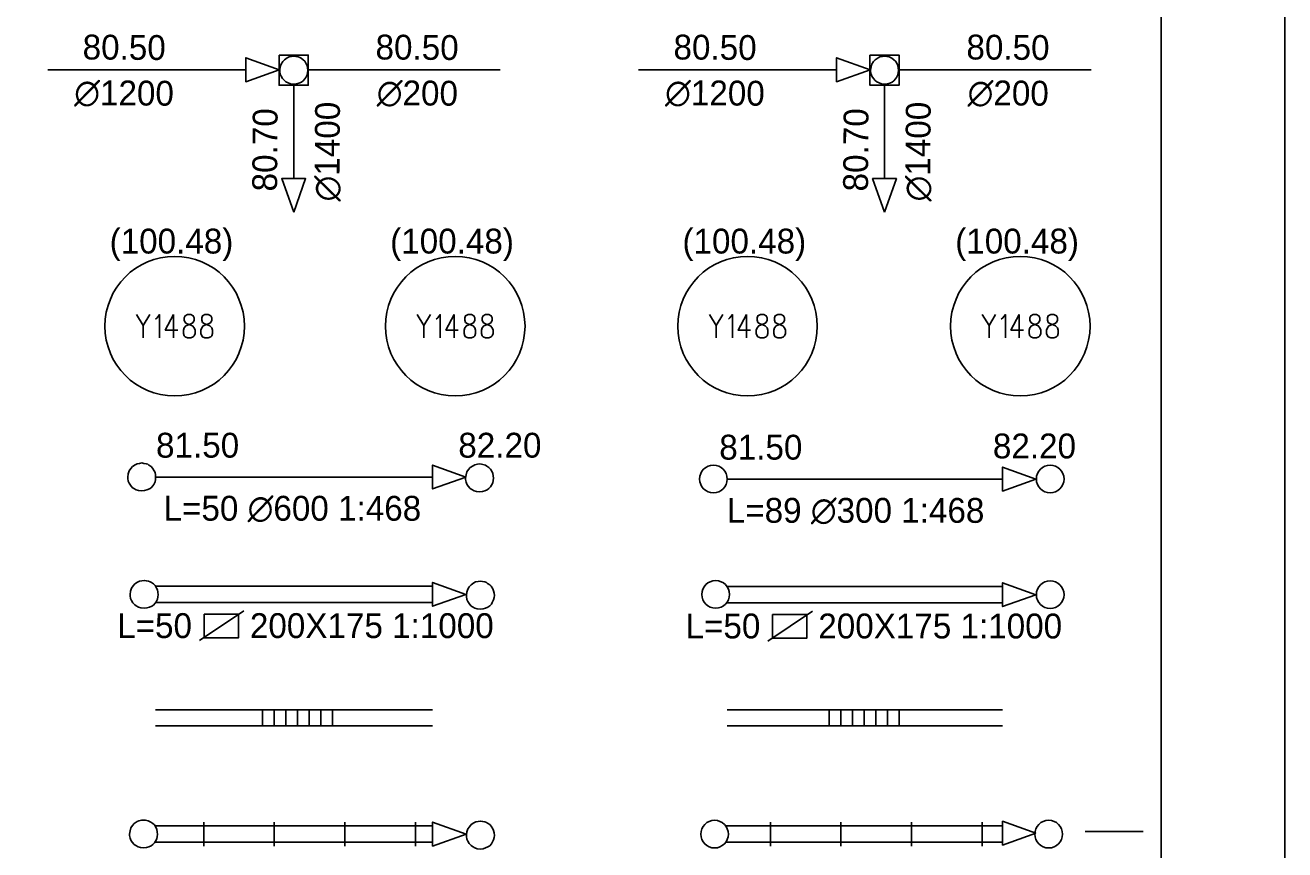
# Model space of a CAD drawing. Extents: x -10 to 1145, y -10 to 821.
# Drawn here: x 1043 to 1145, y 616.2 to 683 of the extents above; entities that cross this region are included whole.
import ezdxf

# ---------------------------------------------------------------- set-up
doc = ezdxf.new("R2010")
doc.units = 0
for name, color, linetype in [('Level 1', 7, 'Continuous'), ('Level 10', 7, 'Continuous'), ('Level 11', 7, 'Continuous'), ('Level 12', 7, 'Continuous'), ('Level 13', 7, 'Continuous'), ('Level 15', 7, 'Continuous'), ('Level 16', 7, 'Continuous'), ('Level 17', 7, 'Continuous'), ('Level 2', 7, 'Continuous'), ('Level 51', 7, 'Continuous'), ('Level 52', 7, 'Continuous'), ('Level 9', 7, 'Continuous')]:
    doc.layers.add(name, color=color, linetype=linetype)

msp = doc.modelspace()

# ---------------------------------------------------------------- linework, layer by layer
at = {"layer": 'Level 1'}
msp.add_line((1133.52, 617.71), (1128.82, 617.71), dxfattribs=at)
at = {"layer": 'Level 10'}
for points in [[(1063.61, 679.35), (1063.61, 679.21), (1063.65, 678.99), (1063.73, 678.83), (1063.84, 678.65), (1063.98, 678.48), (1064.11, 678.39), (1064.3, 678.29), (1064.49, 678.22), (1064.74, 678.2), (1064.97, 678.22), (1065.16, 678.28), (1065.36, 678.36), (1065.5, 678.46), (1065.64, 678.61), (1065.71, 678.73), (1065.82, 678.93), (1065.86, 679.13), (1065.88, 679.3), (1065.86, 679.5), (1065.82, 679.69), (1065.76, 679.83), (1065.63, 680.05), (1065.5, 680.17), (1065.33, 680.28), (1065.23, 680.35), (1065.11, 680.39), (1064.92, 680.43), (1064.75, 680.46), (1064.57, 680.43), (1064.36, 680.39), (1064.21, 680.32), (1063.99, 680.17), (1063.86, 680.01), (1063.73, 679.82), (1063.65, 679.58), (1063.61, 679.32)], [(1111.46, 679.35), (1111.46, 679.21), (1111.5, 678.99), (1111.57, 678.83), (1111.68, 678.65), (1111.83, 678.48), (1111.96, 678.39), (1112.14, 678.29), (1112.34, 678.22), (1112.59, 678.2), (1112.82, 678.22), (1113.01, 678.28), (1113.21, 678.36), (1113.35, 678.46), (1113.48, 678.61), (1113.56, 678.73), (1113.67, 678.93), (1113.7, 679.13), (1113.72, 679.3), (1113.7, 679.5), (1113.67, 679.69), (1113.6, 679.83), (1113.47, 680.05), (1113.35, 680.17), (1113.18, 680.28), (1113.08, 680.35), (1112.96, 680.39), (1112.76, 680.43), (1112.6, 680.46), (1112.41, 680.43), (1112.21, 680.39), (1112.06, 680.32), (1111.84, 680.17), (1111.7, 680.01), (1111.57, 679.82), (1111.5, 679.58), (1111.46, 679.32)], [(1051.3, 646.42), (1051.3, 646.28), (1051.34, 646.06), (1051.41, 645.9), (1051.52, 645.72), (1051.67, 645.55), (1051.8, 645.46), (1051.98, 645.36), (1052.18, 645.29), (1052.43, 645.27), (1052.66, 645.29), (1052.85, 645.35), (1053.05, 645.43), (1053.19, 645.53), (1053.32, 645.68), (1053.4, 645.8), (1053.51, 646), (1053.54, 646.2), (1053.56, 646.37), (1053.54, 646.57), (1053.51, 646.76), (1053.44, 646.9), (1053.31, 647.12), (1053.19, 647.24), (1053.02, 647.35), (1052.92, 647.42), (1052.8, 647.46), (1052.6, 647.5), (1052.44, 647.53), (1052.25, 647.5), (1052.05, 647.46), (1051.9, 647.39), (1051.68, 647.24), (1051.54, 647.08), (1051.41, 646.89), (1051.34, 646.65), (1051.3, 646.39)], [(1078.66, 646.34), (1078.66, 646.2), (1078.7, 645.98), (1078.77, 645.82), (1078.88, 645.64), (1079.03, 645.47), (1079.16, 645.38), (1079.34, 645.28), (1079.54, 645.22), (1079.79, 645.19), (1080.02, 645.22), (1080.21, 645.27), (1080.41, 645.35), (1080.54, 645.45), (1080.68, 645.6), (1080.76, 645.72), (1080.87, 645.93), (1080.9, 646.12), (1080.92, 646.29), (1080.9, 646.49), (1080.87, 646.68), (1080.8, 646.82), (1080.67, 647.04), (1080.54, 647.16), (1080.38, 647.27), (1080.28, 647.34), (1080.16, 647.38), (1079.96, 647.42), (1079.8, 647.45), (1079.61, 647.42), (1079.41, 647.38), (1079.26, 647.31), (1079.04, 647.16), (1078.9, 647), (1078.77, 646.81), (1078.7, 646.57), (1078.66, 646.31)], [(1051.49, 636.92), (1051.49, 636.78), (1051.53, 636.56), (1051.61, 636.4), (1051.72, 636.22), (1051.86, 636.05), (1051.99, 635.96), (1052.18, 635.86), (1052.37, 635.8), (1052.62, 635.77), (1052.85, 635.8), (1053.05, 635.85), (1053.24, 635.93), (1053.38, 636.03), (1053.52, 636.18), (1053.59, 636.3), (1053.7, 636.51), (1053.74, 636.7), (1053.76, 636.87), (1053.74, 637.07), (1053.7, 637.26), (1053.64, 637.4), (1053.51, 637.62), (1053.38, 637.74), (1053.21, 637.85), (1053.11, 637.92), (1052.99, 637.96), (1052.8, 638), (1052.63, 638.03), (1052.45, 638), (1052.24, 637.96), (1052.1, 637.89), (1051.87, 637.74), (1051.74, 637.58), (1051.61, 637.39), (1051.53, 637.15), (1051.49, 636.89)], [(1078.72, 636.85), (1078.72, 636.71), (1078.76, 636.49), (1078.84, 636.33), (1078.95, 636.15), (1079.09, 635.98), (1079.22, 635.89), (1079.41, 635.79), (1079.6, 635.73), (1079.85, 635.7), (1080.08, 635.73), (1080.27, 635.78), (1080.47, 635.87), (1080.61, 635.96), (1080.75, 636.11), (1080.82, 636.23), (1080.93, 636.44), (1080.97, 636.63), (1080.99, 636.8), (1080.97, 637), (1080.93, 637.19), (1080.87, 637.33), (1080.73, 637.55), (1080.61, 637.67), (1080.44, 637.78), (1080.34, 637.85), (1080.22, 637.9), (1080.03, 637.93), (1079.86, 637.96), (1079.67, 637.93), (1079.47, 637.9), (1079.32, 637.82), (1079.1, 637.67), (1078.96, 637.51), (1078.84, 637.32), (1078.76, 637.08), (1078.72, 636.83)], [(1051.45, 617.53), (1051.45, 617.39), (1051.49, 617.17), (1051.56, 617.01), (1051.67, 616.83), (1051.82, 616.66), (1051.95, 616.57), (1052.13, 616.47), (1052.33, 616.4), (1052.58, 616.38), (1052.81, 616.4), (1053, 616.46), (1053.19, 616.54), (1053.33, 616.64), (1053.47, 616.79), (1053.55, 616.91), (1053.66, 617.11), (1053.69, 617.31), (1053.71, 617.47), (1053.69, 617.68), (1053.66, 617.87), (1053.59, 618.01), (1053.46, 618.23), (1053.33, 618.35), (1053.17, 618.46), (1053.07, 618.52), (1052.95, 618.57), (1052.75, 618.61), (1052.58, 618.63), (1052.4, 618.61), (1052.2, 618.57), (1052.05, 618.5), (1051.83, 618.35), (1051.69, 618.18), (1051.56, 618), (1051.49, 617.76), (1051.45, 617.5)], [(1078.73, 617.44), (1078.73, 617.3), (1078.77, 617.08), (1078.84, 616.92), (1078.95, 616.73), (1079.1, 616.57), (1079.23, 616.48), (1079.41, 616.38), (1079.6, 616.31), (1079.85, 616.28), (1080.09, 616.31), (1080.28, 616.37), (1080.47, 616.45), (1080.61, 616.55), (1080.75, 616.7), (1080.82, 616.82), (1080.93, 617.02), (1080.97, 617.22), (1080.99, 617.38), (1080.97, 617.59), (1080.93, 617.78), (1080.87, 617.92), (1080.74, 618.14), (1080.61, 618.26), (1080.44, 618.37), (1080.34, 618.43), (1080.22, 618.48), (1080.03, 618.52), (1079.86, 618.55), (1079.68, 618.52), (1079.48, 618.48), (1079.33, 618.41), (1079.11, 618.26), (1078.97, 618.09), (1078.84, 617.91), (1078.77, 617.67), (1078.73, 617.41)]]:
    msp.add_lwpolyline(points, dxfattribs=at)
for centre in [(1098.73, 646.23), (1126, 646.23), (1098.91, 636.89), (1126, 636.87), (1098.82, 617.49), (1125.88, 617.49)]:
    msp.add_circle(centre, 1.12, dxfattribs=at)
at = {"layer": 'Level 11'}
for centre in [(1055.1, 658.6), (1077.82, 658.6), (1101.49, 658.6), (1123.58, 658.6)]:
    msp.add_circle(centre, 5.65, dxfattribs=at)
at = {"layer": 'Level 12'}
for points in [[(1052.02, 659.54), (1052.56, 658.65), (1052.56, 657.66)], [(1053.09, 659.54), (1052.56, 658.65)], [(1053.55, 659.17), (1053.68, 659.27), (1053.88, 659.54), (1053.88, 657.66)], [(1055.01, 659.54), (1054.34, 658.28), (1055.35, 658.28)], [(1055.01, 659.54), (1055.01, 657.66)], [(1056.14, 659.54), (1055.94, 659.45), (1055.87, 659.27), (1055.87, 659.08), (1055.94, 658.9), (1056.07, 658.81), (1056.34, 658.72), (1056.54, 658.63), (1056.69, 658.46), (1056.75, 658.28), (1056.75, 658.01), (1056.69, 657.83), (1056.61, 657.74), (1056.41, 657.66), (1056.14, 657.66), (1055.94, 657.74), (1055.87, 657.83), (1055.81, 658.01), (1055.81, 658.28), (1055.87, 658.46), (1056.01, 658.63), (1056.21, 658.72), (1056.47, 658.81), (1056.61, 658.9), (1056.69, 659.08), (1056.69, 659.27), (1056.61, 659.45), (1056.41, 659.54), (1056.14, 659.54)], [(1057.55, 659.54), (1057.35, 659.45), (1057.29, 659.27), (1057.29, 659.08), (1057.35, 658.9), (1057.49, 658.81), (1057.75, 658.72), (1057.95, 658.63), (1058.1, 658.46), (1058.16, 658.28), (1058.16, 658.01), (1058.1, 657.83), (1058.02, 657.74), (1057.82, 657.66), (1057.55, 657.66), (1057.35, 657.74), (1057.29, 657.83), (1057.22, 658.01), (1057.22, 658.28), (1057.29, 658.46), (1057.42, 658.63), (1057.62, 658.72), (1057.89, 658.81), (1058.02, 658.9), (1058.1, 659.08), (1058.1, 659.27), (1058.02, 659.45), (1057.82, 659.54), (1057.55, 659.54)], [(1074.73, 659.54), (1075.28, 658.65), (1075.28, 657.66)], [(1075.81, 659.54), (1075.28, 658.65)], [(1076.27, 659.17), (1076.4, 659.27), (1076.6, 659.54), (1076.6, 657.66)], [(1077.73, 659.54), (1077.06, 658.28), (1078.07, 658.28)], [(1077.73, 659.54), (1077.73, 657.66)], [(1078.86, 659.54), (1078.66, 659.45), (1078.59, 659.27), (1078.59, 659.08), (1078.66, 658.9), (1078.79, 658.81), (1079.06, 658.72), (1079.26, 658.63), (1079.41, 658.46), (1079.47, 658.28), (1079.47, 658.01), (1079.41, 657.83), (1079.33, 657.74), (1079.13, 657.66), (1078.86, 657.66), (1078.66, 657.74), (1078.59, 657.83), (1078.53, 658.01), (1078.53, 658.28), (1078.59, 658.46), (1078.73, 658.63), (1078.93, 658.72), (1079.19, 658.81), (1079.33, 658.9), (1079.41, 659.08), (1079.41, 659.27), (1079.33, 659.45), (1079.13, 659.54), (1078.86, 659.54)], [(1080.27, 659.54), (1080.07, 659.45), (1080.01, 659.27), (1080.01, 659.08), (1080.07, 658.9), (1080.21, 658.81), (1080.47, 658.72), (1080.67, 658.63), (1080.82, 658.46), (1080.88, 658.28), (1080.88, 658.01), (1080.82, 657.83), (1080.74, 657.74), (1080.54, 657.66), (1080.27, 657.66), (1080.07, 657.74), (1080.01, 657.83), (1079.94, 658.01), (1079.94, 658.28), (1080.01, 658.46), (1080.14, 658.63), (1080.34, 658.72), (1080.61, 658.81), (1080.74, 658.9), (1080.82, 659.08), (1080.82, 659.27), (1080.74, 659.45), (1080.54, 659.54), (1080.27, 659.54)], [(1098.41, 659.54), (1098.95, 658.65), (1098.95, 657.66)], [(1099.49, 659.54), (1098.95, 658.65)], [(1099.94, 659.17), (1100.07, 659.27), (1100.27, 659.54), (1100.27, 657.66)], [(1101.4, 659.54), (1100.73, 658.28), (1101.74, 658.28)], [(1101.4, 659.54), (1101.4, 657.66)], [(1102.53, 659.54), (1102.33, 659.45), (1102.26, 659.27), (1102.26, 659.08), (1102.33, 658.9), (1102.47, 658.81), (1102.73, 658.72), (1102.93, 658.63), (1103.08, 658.46), (1103.14, 658.28), (1103.14, 658.01), (1103.08, 657.83), (1103, 657.74), (1102.8, 657.66), (1102.53, 657.66), (1102.33, 657.74), (1102.26, 657.83), (1102.2, 658.01), (1102.2, 658.28), (1102.26, 658.46), (1102.4, 658.63), (1102.6, 658.72), (1102.87, 658.81), (1103, 658.9), (1103.08, 659.08), (1103.08, 659.27), (1103, 659.45), (1102.8, 659.54), (1102.53, 659.54)], [(1103.94, 659.54), (1103.74, 659.45), (1103.68, 659.27), (1103.68, 659.08), (1103.74, 658.9), (1103.88, 658.81), (1104.14, 658.72), (1104.34, 658.63), (1104.49, 658.46), (1104.56, 658.28), (1104.56, 658.01), (1104.49, 657.83), (1104.41, 657.74), (1104.21, 657.66), (1103.94, 657.66), (1103.74, 657.74), (1103.68, 657.83), (1103.61, 658.01), (1103.61, 658.28), (1103.68, 658.46), (1103.81, 658.63), (1104.01, 658.72), (1104.28, 658.81), (1104.41, 658.9), (1104.49, 659.08), (1104.49, 659.27), (1104.41, 659.45), (1104.21, 659.54), (1103.94, 659.54)], [(1120.5, 659.54), (1121.05, 658.65), (1121.05, 657.66)], [(1121.58, 659.54), (1121.05, 658.65)], [(1122.03, 659.17), (1122.17, 659.27), (1122.37, 659.54), (1122.37, 657.66)], [(1123.49, 659.54), (1122.82, 658.28), (1123.84, 658.28)], [(1123.49, 659.54), (1123.49, 657.66)], [(1124.63, 659.54), (1124.43, 659.45), (1124.36, 659.27), (1124.36, 659.08), (1124.43, 658.9), (1124.56, 658.81), (1124.83, 658.72), (1125.03, 658.63), (1125.17, 658.46), (1125.24, 658.28), (1125.24, 658.01), (1125.17, 657.83), (1125.09, 657.74), (1124.89, 657.66), (1124.63, 657.66), (1124.43, 657.74), (1124.36, 657.83), (1124.29, 658.01), (1124.29, 658.28), (1124.36, 658.46), (1124.49, 658.63), (1124.69, 658.72), (1124.96, 658.81), (1125.09, 658.9), (1125.17, 659.08), (1125.17, 659.27), (1125.09, 659.45), (1124.89, 659.54), (1124.63, 659.54)], [(1126.04, 659.54), (1125.84, 659.45), (1125.77, 659.27), (1125.77, 659.08), (1125.84, 658.9), (1125.97, 658.81), (1126.24, 658.72), (1126.44, 658.63), (1126.58, 658.46), (1126.65, 658.28), (1126.65, 658.01), (1126.58, 657.83), (1126.51, 657.74), (1126.3, 657.66), (1126.04, 657.66), (1125.84, 657.74), (1125.77, 657.83), (1125.7, 658.01), (1125.7, 658.28), (1125.77, 658.46), (1125.9, 658.63), (1126.1, 658.72), (1126.37, 658.81), (1126.51, 658.9), (1126.58, 659.08), (1126.58, 659.27), (1126.51, 659.45), (1126.3, 659.54), (1126.04, 659.54)]]:
    msp.add_lwpolyline(points, dxfattribs=at)
at = {"layer": 'Level 15'}
for p, q in [((1044.82, 679.36), (1060.86, 679.36)), ((1065.92, 679.36), (1081.47, 679.36)), ((1092.67, 679.36), (1108.7, 679.36)), ((1113.77, 679.36), (1129.32, 679.36)), ((1064.74, 678.1), (1064.74, 670.59)), ((1112.58, 678.1), (1112.58, 670.59)), ((1053.56, 646.39), (1075.98, 646.39)), ((1099.85, 646.23), (1122.15, 646.23)), ((1053.56, 637.55), (1075.98, 637.55)), ((1099.85, 637.53), (1122.15, 637.53)), ((1053.56, 636.23), (1075.98, 636.23)), ((1099.85, 636.21), (1122.15, 636.21)), ((1053.56, 627.56), (1075.98, 627.56)), ((1062.22, 627.56), (1062.22, 626.25)), ((1063.17, 627.56), (1063.17, 626.25)), ((1064.11, 627.56), (1064.11, 626.25)), ((1065.05, 627.56), (1065.05, 626.25)), ((1065.99, 627.56), (1065.99, 626.25)), ((1066.93, 627.56), (1066.93, 626.25)), ((1067.87, 627.56), (1067.87, 626.25)), ((1099.85, 627.56), (1122.15, 627.56)), ((1108.11, 627.56), (1108.11, 626.25)), ((1109.05, 627.56), (1109.05, 626.25)), ((1110, 627.56), (1110, 626.25)), ((1110.94, 627.56), (1110.94, 626.25)), ((1111.88, 627.56), (1111.88, 626.25)), ((1112.82, 627.56), (1112.82, 626.25)), ((1113.76, 627.56), (1113.76, 626.25)), ((1053.56, 626.25), (1075.98, 626.25)), ((1099.85, 626.25), (1122.15, 626.25)), ((1057.45, 618.46), (1057.45, 616.52)), ((1063.17, 618.46), (1063.17, 616.52)), ((1068.88, 618.46), (1068.88, 616.52)), ((1074.59, 618.46), (1074.59, 616.52)), ((1103.34, 618.46), (1103.34, 616.52)), ((1109.05, 618.46), (1109.05, 616.52)), ((1114.77, 618.46), (1114.77, 616.52)), ((1120.48, 618.46), (1120.48, 616.52)), ((1053.56, 618.15), (1075.98, 618.15)), ((1099.73, 618.15), (1122.15, 618.15)), ((1053.56, 616.83), (1075.98, 616.83)), ((1099.73, 616.83), (1122.15, 616.83))]:
    msp.add_line(p, q, dxfattribs=at)
at = {"layer": 'Level 16'}
for points in [[(1063.56, 679.36), (1060.86, 680.32), (1060.86, 678.39)], [(1111.41, 679.36), (1108.7, 680.32), (1108.7, 678.39)], [(1064.74, 667.84), (1065.7, 670.54), (1063.77, 670.54)], [(1112.58, 667.84), (1113.55, 670.54), (1111.62, 670.54)], [(1078.68, 646.39), (1075.98, 647.36), (1075.98, 645.43)], [(1124.85, 646.23), (1122.15, 647.2), (1122.15, 645.26)], [(1078.68, 636.89), (1075.98, 637.86), (1075.98, 635.93)], [(1124.85, 636.87), (1122.15, 637.84), (1122.15, 635.9)], [(1078.7, 617.49), (1075.99, 618.46), (1075.99, 616.52)], [(1124.85, 617.57), (1122.15, 618.53), (1122.15, 616.6)]]:
    msp.add_lwpolyline(points, close=True, dxfattribs=at)
at = {"layer": 'Level 17'}
for p, q in [((1057.11, 633.15), (1060.71, 635.56)), ((1057.11, 633.15), (1060.71, 635.56)), ((1103.14, 633.12), (1106.74, 635.54)), ((1057.49, 635.3), (1060.32, 635.3))]:
    msp.add_line(p, q, dxfattribs=at)
for points in [[(1057.49, 635.3), (1060.27, 635.3), (1060.27, 633.38), (1057.49, 633.38)], [(1103.52, 635.27), (1106.3, 635.27), (1106.3, 633.36), (1103.52, 633.36)]]:
    msp.add_lwpolyline(points, close=True, dxfattribs=at)
at = {"layer": 'Level 2'}
msp.add_line((1133.52, 617.71), (1128.82, 617.71), dxfattribs=at)
at = {"layer": 'Level 51'}
msp.add_lwpolyline([(-10, -10), (1145, -10), (1145, 821), (-10, 821)], close=True, dxfattribs=at)
at = {"layer": 'Level 52'}
msp.add_lwpolyline([(965, 287), (1135, 287), (1135, 811), (965, 811)], close=True, dxfattribs=at)
at = {"layer": 'Level 9'}
for points in [[(1063.55, 680.54), (1065.92, 680.54), (1065.92, 678.1), (1063.55, 678.1)], [(1111.4, 680.54), (1113.77, 680.54), (1113.77, 678.1), (1111.4, 678.1)]]:
    msp.add_lwpolyline(points, close=True, dxfattribs=at)

# ---------------------------------------------------------------- texts
at = {"layer": 'Level 13'}
for p in [(1049.83, 664.48), (1072.55, 664.48), (1096.22, 664.48), (1118.31, 664.48)]:
    msp.add_text('(100.48)', height=2.012, rotation=360, dxfattribs=at).set_placement(p)
at = {"layer": 'Level 17'}
for s, height, rotation, p in [('80.50', 2.012, 359.5872, (1047.64, 680.19)), ('80.50', 2.012, 359.5872, (1071.36, 680.19)), ('80.50', 2.012, 359.5872, (1095.49, 680.19)), ('80.50', 2.012, 359.5872, (1119.21, 680.19)), ('∅1200', 2.012, 359.5872, (1046.96, 676.5)), ('∅200', 2.012, 359.5872, (1071.46, 676.49)), ('∅1200', 2.012, 359.5872, (1094.81, 676.5)), ('∅200', 2.012, 359.5872, (1119.31, 676.49)), ('∅1400', 2.012, 89.5872, (1068.43, 668.69)), ('∅1400', 2.012, 89.5872, (1116.27, 668.69)), ('80.70', 2.012, 89.5872, (1063.39, 669.5)), ('80.70', 2.012, 89.5872, (1111.24, 669.5)), ('81.50', 2.012, 360, (1053.59, 647.96)), ('82.20', 2.012, 360, (1078.07, 647.96)), ('81.50', 2.012, 360, (1099.2, 647.8)), ('82.20', 2.012, 360, (1121.36, 647.9)), ('L=50 ∅600 1:468', 2.0119, 359.987, (1054.2, 642.86)), ('L=89 ∅300 1:468', 2.0119, 359.987, (1099.81, 642.69)), ('L=50', 2.012, 359.987, (1050.44, 633.36)), ('200X175 1:1000', 2.0119, 359.987, (1061.19, 633.36)), ('L=50', 2.012, 359.987, (1096.47, 633.33)), ('200X175 1:1000', 2.0119, 359.987, (1107.22, 633.33))]:
    msp.add_text(s, height=height, rotation=rotation, dxfattribs=at).set_placement(p)

doc.saveas('drawing.dxf')
